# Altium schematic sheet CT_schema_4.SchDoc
size 297 x 173 mm
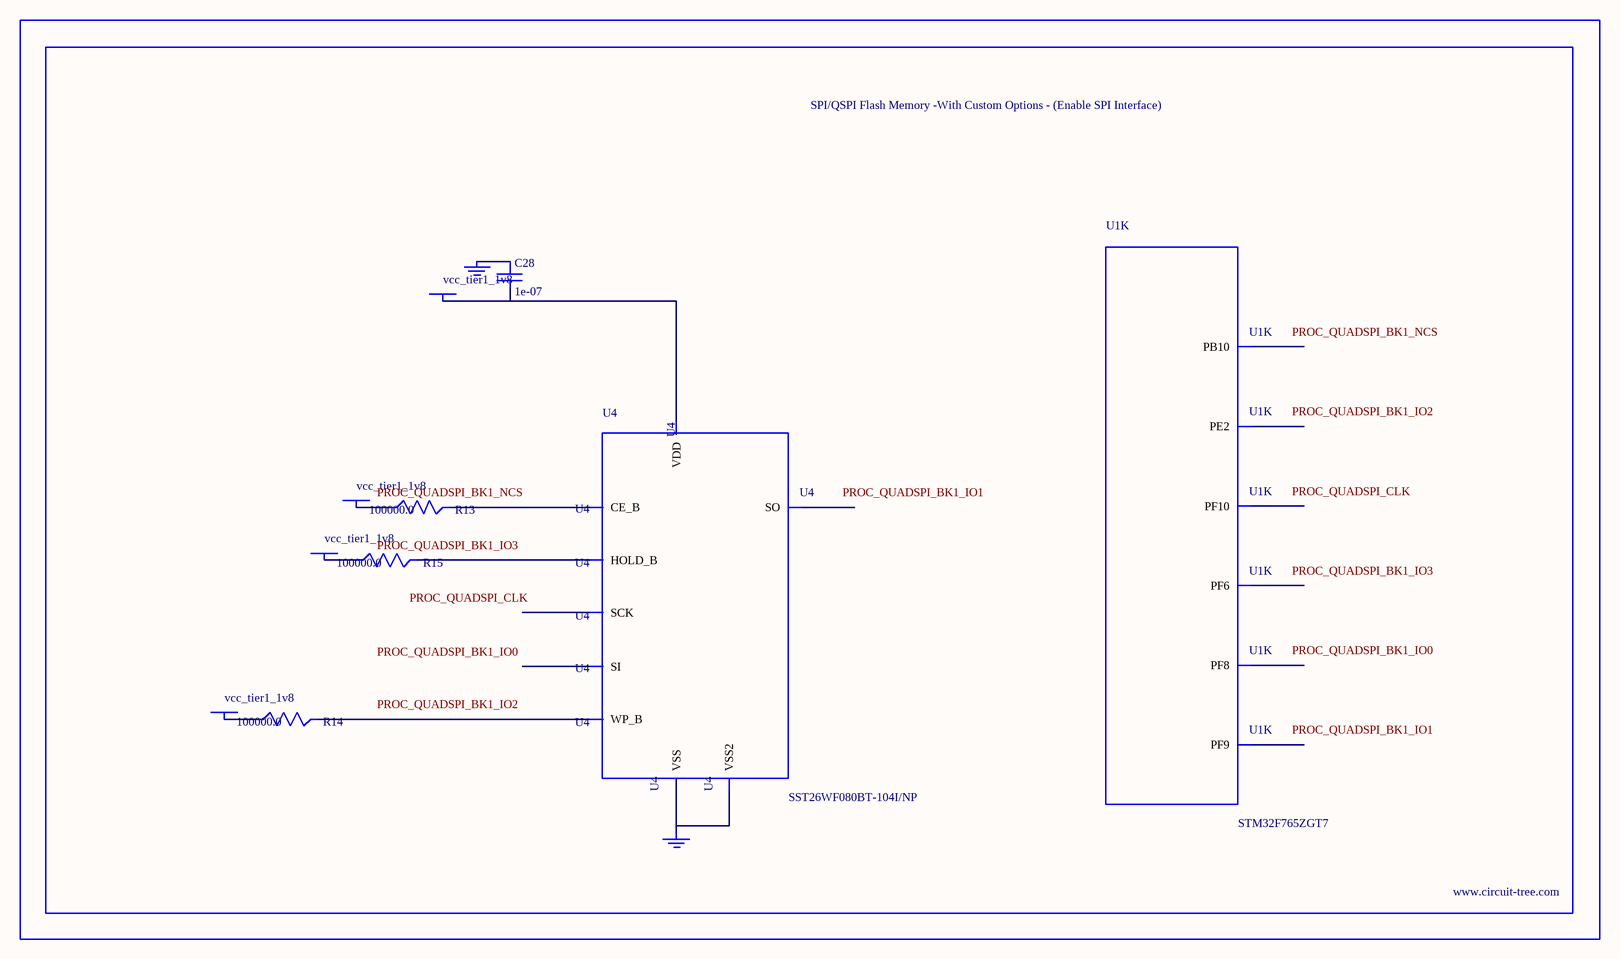
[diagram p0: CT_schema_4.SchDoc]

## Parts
BORDER3  (no value)
C28  1e-07  [C0402]
GND_INSTANCE_3_0  (no value)
GND_INSTANCE_3_1  (no value)
POWER_INSTANCE_3_0  vcc_tier1_1v8
POWER_INSTANCE_3_1  vcc_tier1_1v8
POWER_INSTANCE_3_2  vcc_tier1_1v8
POWER_INSTANCE_3_3  vcc_tier1_1v8
R13  100000.0  [R0603]
R14  100000.0  [R0603]
R15  100000.0  [R0603]
U1  STM32F765ZGT7  [LQFP144]  (part K of 11)
U4  SST26WF080BT-104I/NP  [USON-8]

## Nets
NetC28_1: C28.1 GND_INSTANCE_3_0.0(GND)
NetC28_2: C28.2 POWER_INSTANCE_3_3.0(PWR) U4.8(VDD)
NetGND_INSTANCE_3_1_0: GND_INSTANCE_3_1.0(GND) U4.4(VSS) U4.9(VSS2)
NetPOWER_INSTANCE_3_0_0: POWER_INSTANCE_3_0.0(PWR) R13.1
NetPOWER_INSTANCE_3_1_0: POWER_INSTANCE_3_1.0(PWR) R14.1
NetPOWER_INSTANCE_3_2_0: POWER_INSTANCE_3_2.0(PWR) R15.1
NetR13_2: R13.2 U4.1(CE_B)
NetR14_2: R14.2 U4.3(WP_B)
NetR15_2: R15.2 U4.7(HOLD_B)

Not connected (* = marked no-connect by the designer): U1 1(PE2) 18(PF6) 20(PF8) 21(PF9) 22(PF10) 69(PB10); U4 2(SO) 5(SI) 6(SCK)

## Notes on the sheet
- Labels drawn without touching a wire or pin: PROC_QUADSPI_BK1_IO0, PROC_QUADSPI_BK1_IO1, PROC_QUADSPI_BK1_IO2, PROC_QUADSPI_BK1_IO3, PROC_QUADSPI_BK1_NCS, PROC_QUADSPI_CLK

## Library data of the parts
BORDER3 = BORDER_PAGE3
C28 = C0402C104K3RACTU
GND_INSTANCE_3_0 GND_INSTANCE_3_1 = GND
POWER_INSTANCE_3_0-POWER_INSTANCE_3_3 = PWR
R13-R15 = RC0603JR-07100KL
